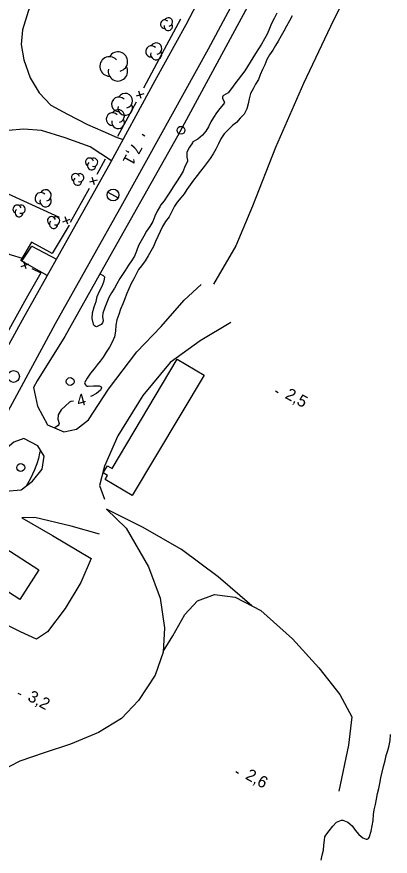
# Model space of a CAD drawing. Extents: x 219136 to 222520, y 5421589 to 5424530.
# Drawn here: x 221431.4 to 221526.7, y 5422722 to 5422936.2 of the extents above; entities that cross this region are included whole.
import ezdxf

# ---------------------------------------------------------------- set-up
doc = ezdxf.new("R2010")
doc.units = 0
for name, color, linetype in [('Level 19', 7, 'Continuous'), ('Level 2', 7, 'Continuous'), ('Level 21', 7, 'Continuous'), ('Level 22', 7, 'Continuous'), ('Level 3', 7, 'Continuous'), ('Level 31', 7, 'Continuous'), ('Level 36', 7, 'Continuous'), ('Level 37', 7, 'Continuous'), ('Level 4', 7, 'Continuous'), ('Level 44', 7, 'Continuous')]:
    doc.layers.add(name, color=color, linetype=linetype)

msp = doc.modelspace()

# ---------------------------------------------------------------- linework, layer by layer
at = {"layer": 'Level 19'}
for points in [[(221444.73, 5422964.58), (221440.63, 5422955.36), (221437.41, 5422946.13), (221434.29, 5422937.53), (221432.86, 5422932.84), (221432.52, 5422929.08), (221433.14, 5422925.22), (221434.77, 5422920.64), (221437.12, 5422916.8), (221440.11, 5422913.61), (221444.29, 5422911.34), (221449.43, 5422908.7), (221453.33, 5422907), (221456.97, 5422905.38), (221458.52, 5422904.9), (221458.52, 5422904.9)], [(221455.56, 5422899.45), (221450.13, 5422902.97), (221443.75, 5422905.28), (221437.65, 5422907.16), (221433.18, 5422907.51), (221429.15, 5422907.19), (221426.47, 5422906.23), (221424.66, 5422905.18), (221423.3, 5422905.9), (221423.99, 5422907.81)], [(221439.15, 5422870.13), (221432.69, 5422873.79), (221435.21, 5422877.69), (221441.53, 5422874.38)], [(221435.61, 5422841.61), (221435.61, 5422841.61), (221436.65, 5422836.82), (221439.23, 5422832.1), (221443.38, 5422830.24), (221446.65, 5422830.99), (221449.7, 5422833.36), (221454.79, 5422841.19), (221462.04, 5422850.67), (221468.26, 5422857.16), (221474.11, 5422863.89), (221478.48, 5422867.89)], [(221486.07, 5422858.15), (221478.17, 5422853.46), (221470.54, 5422848), (221463.6, 5422839.56), (221457.18, 5422829.25), (221453.81, 5422821.54), (221452.51, 5422816.61), (221453.74, 5422813.07)], [(221426.88, 5422822.1), (221426.47, 5422817.72), (221428.51, 5422815.17), (221432.5, 5422815.48), (221435.41, 5422817.66), (221437.85, 5422820.74), (221438.38, 5422824.05), (221436.71, 5422826.7), (221433.19, 5422828.61), (221430.64, 5422827.65), (221428.31, 5422825.67), (221427.3, 5422823.23), (221426.88, 5422822.1)], [(221452.48, 5422804.16), (221445.25, 5422806.19), (221435.99, 5422808.42), (221432.65, 5422808.36), (221440.53, 5422803.81), (221450.33, 5422797.93), (221447.77, 5422791.86), (221443.71, 5422785.23), (221439.24, 5422779.2), (221436.41, 5422777.39), (221432.3, 5422779.27), (221426.3, 5422782.25), (221417.54, 5422786.7), (221413.86, 5422787.79), (221413.2, 5422787.46)]]:
    msp.add_lwpolyline(points, dxfattribs=at)
at = {"layer": 'Level 2'}
for points in [[(221497.8, 5422937.14), (221497.08, 5422935.77), (221496.43, 5422934.5), (221495.87, 5422933.24), (221495.28, 5422931.78), (221494.62, 5422930.53), (221493.89, 5422929.18), (221493.12, 5422928), (221492.37, 5422926.85), (221491.65, 5422925.73), (221490.93, 5422924.63), (221490.29, 5422923.47), (221489.59, 5422922.42), (221488.72, 5422921.27), (221487.92, 5422920.17), (221487.07, 5422919.07), (221486.19, 5422917.9)], [(221501.7, 5422936.4), (221501, 5422935.13), (221500.28, 5422933.79), (221499.59, 5422932.55), (221498.9, 5422931.31), (221498.13, 5422929.94), (221497.45, 5422928.84), (221496.73, 5422927.68), (221495.92, 5422926.47), (221495.21, 5422925.26), (221494.68, 5422923.97), (221494.16, 5422922.77), (221493.56, 5422921.36), (221493.06, 5422920.21), (221492.34, 5422919), (221491.7, 5422917.83)], [(221491.7, 5422917.83), (221491.06, 5422916.59), (221490.72, 5422915.27), (221490.45, 5422913.95), (221490.15, 5422912.69), (221489.41, 5422911.38), (221488.45, 5422910.3), (221487.48, 5422909.19), (221486.5, 5422908.41), (221485.37, 5422907.36), (221484.33, 5422906.32), (221483.51, 5422905.06), (221482.85, 5422903.75), (221482.2, 5422902.41), (221481.48, 5422901.19), (221480.75, 5422900.06), (221480, 5422898.97), (221479.19, 5422897.95), (221478.25, 5422896.76), (221477.4, 5422895.71), (221476.5, 5422894.54), (221475.61, 5422893.29), (221474.81, 5422892.14), (221474.09, 5422891.04), (221473.28, 5422889.95), (221472.35, 5422888.92), (221471.66, 5422887.87), (221470.96, 5422886.53), (221470.29, 5422885.17), (221469.38, 5422883.94), (221468.61, 5422882.68), (221468.03, 5422881.36), (221467.41, 5422880.15), (221466.83, 5422878.83), (221466.25, 5422877.57), (221465.61, 5422876.34), (221464.96, 5422875.21), (221464.12, 5422873.93), (221463.23, 5422872.66), (221462.46, 5422871.67), (221461.87, 5422870.49), (221461.29, 5422869.33), (221460.62, 5422868.15), (221459.97, 5422866.79), (221459.38, 5422865.41), (221458.95, 5422864.23), (221458.43, 5422862.97), (221457.9, 5422861.59), (221457.4, 5422860.22), (221456.93, 5422858.89), (221456.67, 5422857.48), (221456.57, 5422855.96), (221456.3, 5422854.52), (221455.73, 5422853.16), (221455.02, 5422851.85), (221454.21, 5422850.58), (221453.45, 5422849.33), (221452.69, 5422848.31), (221451.88, 5422847.34), (221451.1, 5422846.33), (221450.21, 5422845.24), (221449.32, 5422843.98), (221448.7, 5422842.75), (221448.71, 5422842.49), (221448.88, 5422842.26)], [(221486.19, 5422917.9), (221485.32, 5422916.82), (221484.14, 5422916.14), (221483.95, 5422915.94), (221483.87, 5422915.65), (221483.88, 5422915.4), (221484.01, 5422915.16), (221484.39, 5422914.43), (221484.32, 5422914.16), (221484.19, 5422913.93), (221483.22, 5422912.79), (221482.39, 5422911.7), (221481.63, 5422910.5), (221480.89, 5422909.36), (221480.29, 5422908.15), (221479.68, 5422907), (221478.77, 5422905.94), (221477.61, 5422905), (221476.36, 5422904.28), (221476.24, 5422904.02), (221475.44, 5422902.9), (221474.81, 5422901.67), (221474.78, 5422900.33), (221475.01, 5422899.56), (221474.93, 5422899.28), (221474.28, 5422898.01), (221473.84, 5422896.83), (221473.13, 5422895.56), (221472.13, 5422894.06), (221471.28, 5422892.82), (221470.63, 5422891.7), (221469.8, 5422890.45), (221468.97, 5422889.26), (221468.06, 5422888.14), (221467.96, 5422887.88), (221467.25, 5422886.61), (221466.64, 5422885.3), (221466.1, 5422883.98), (221465.39, 5422882.7), (221464.52, 5422881.48), (221463.82, 5422880.24), (221463.15, 5422879.01), (221462.48, 5422877.81), (221461.94, 5422876.34), (221461.4, 5422875.1), (221460.64, 5422873.94), (221459.89, 5422872.83), (221459.05, 5422871.47), (221458.4, 5422870.39), (221457.67, 5422869.38), (221456.93, 5422868.01), (221456.3, 5422866.93), (221455.59, 5422865.78), (221454.89, 5422864.54), (221454.35, 5422863.25), (221453.86, 5422862.04), (221453.36, 5422860.59), (221453.28, 5422859.69), (221453.42, 5422858.58), (221453.26, 5422858.08), (221452.95, 5422857.63), (221451.74, 5422857.04), (221451.47, 5422857.13), (221451.26, 5422857.3), (221451.06, 5422857.52)], [(221433.08, 5422874.39), (221430.88, 5422875.12), (221429.41, 5422875.52), (221428.17, 5422876.34), (221427.05, 5422877.27), (221425.78, 5422877.81), (221424.5, 5422878.22), (221423.07, 5422878.43), (221421.74, 5422878.54), (221420.36, 5422878.61), (221418.92, 5422878.73), (221417.5, 5422879.14), (221416.17, 5422879.1), (221414.79, 5422878.66), (221413.27, 5422878.51), (221412, 5422878.68)], [(221451.06, 5422857.52), (221450.94, 5422857.76), (221450.6, 5422859.16), (221450.71, 5422860.66), (221451.17, 5422862.14), (221451.63, 5422863.54), (221451.94, 5422864.84), (221452.47, 5422866.14), (221453.18, 5422867.45), (221453.72, 5422868.79), (221453.88, 5422869.72), (221453.71, 5422869.93), (221453.49, 5422870.09), (221452.58, 5422870.56)], [(221448.88, 5422842.26), (221449.09, 5422842.09), (221449.33, 5422841.96), (221449.61, 5422841.9), (221450.99, 5422842), (221452.42, 5422842.02), (221452.94, 5422841.75), (221453, 5422841.48), (221452.93, 5422841.22), (221452.77, 5422840.93), (221451.69, 5422840.04), (221450.46, 5422839.38), (221450.22, 5422839.26)], [(221445.87, 5422838.11), (221445.15, 5422837.99), (221444.86, 5422837.84), (221443.72, 5422836.83), (221442.74, 5422835.85), (221441.9, 5422834.61), (221441.86, 5422833.53), (221442.24, 5422832.44), (221442.1, 5422832.17), (221441.91, 5422831.92), (221441.08, 5422831.27)], [(221437.45, 5422825.53), (221437.2, 5422824.84), (221436.93, 5422823.46), (221436.46, 5422822.07), (221435.89, 5422820.62), (221435.37, 5422819.48), (221434.84, 5422818.34), (221434.13, 5422816.97), (221433.77, 5422816.43)]]:
    msp.add_lwpolyline(points, dxfattribs=at)
at = {"layer": 'Level 21'}
for points in [[(221660.64, 5423258.98), (221639.04, 5423219.11), (221616.62, 5423177.95), (221598.48, 5423145.47), (221572.5, 5423097.61), (221544.2, 5423045.77), (221525.59, 5423011.52), (221501.12, 5422966.85), (221480.22, 5422927.93), (221458.39, 5422888.43), (221441.16, 5422857.84), (221426.14, 5422830.08), (221397.61, 5422779.56)], [(221573.68, 5423090.42), (221550.76, 5423048.84), (221524.85, 5423002.21), (221513.34, 5422981.11), (221496.53, 5422950.29), (221472.38, 5422905.69), (221452.73, 5422870.82), (221443.68, 5422854.61), (221436.62, 5422843.25), (221435.61, 5422841.61)], [(221423.8, 5422850.98), (221425.45, 5422850.43), (221426.75, 5422850.45), (221428.3, 5422851.3), (221429.4, 5422852.61), (221432.84, 5422858.87), (221454.87, 5422898.19), (221466.7, 5422919.93), (221474.59, 5422934.2), (221477.45, 5422939.57), (221478.51, 5422941.89), (221478.75, 5422943.99), (221478.29, 5422946.25), (221477.27, 5422947.93), (221476.62, 5422949.49)]]:
    msp.add_lwpolyline(points, dxfattribs=at)
at = {"layer": 'Level 22'}
for points in [[(221513.34, 5422981.11), (221513.79, 5422980.18), (221515.67, 5422975.98), (221518.52, 5422969.98), (221520.79, 5422963.3), (221521.05, 5422955.96), (221519.28, 5422949.47), (221512.27, 5422935.35), (221504.62, 5422919.16), (221497.4, 5422902.81), (221491.57, 5422887.89), (221487.28, 5422877.77), (221481.59, 5422867.92)], [(221454.3, 5422810.51), (221459.28, 5422805.72), (221464.97, 5422795.86), (221467.99, 5422787.86), (221469.08, 5422780.24), (221468.76, 5422774.06), (221466.75, 5422768.18), (221462.44, 5422761.73), (221458.14, 5422757.08), (221452.23, 5422753.51), (221445.07, 5422750.57), (221438.34, 5422748.37), (221432.15, 5422746.2), (221426.76, 5422743.55), (221422.19, 5422739.04), (221418.14, 5422733.43), (221412.6, 5422722.52), (221397.76, 5422693.4), (221390.31, 5422680.23), (221384.4, 5422671.25), (221379.74, 5422663.83)], [(221491.42, 5422785.85), (221482.77, 5422793.29), (221473.45, 5422800.29), (221463.62, 5422805.85), (221454.3, 5422810.51)], [(221468.77, 5422774.18), (221471.22, 5422778.2), (221474.28, 5422783.63), (221477.55, 5422787.11), (221481.89, 5422788.74), (221487.17, 5422788.05), (221493.7, 5422784.67), (221501.82, 5422777.48), (221508.51, 5422770.03), (221513.87, 5422763.24), (221516.97, 5422757.55), (221516.1, 5422750.35), (221513.59, 5422738.55)]]:
    msp.add_lwpolyline(points, dxfattribs=at)
at = {"layer": 'Level 3'}
for p, q in [((221463.38, 5422906.22), (221464.08, 5422905.84)), ((221497.43, 5422840.72), (221498.14, 5422840.34)), ((221431.68, 5422763.6), (221432.38, 5422763.21)), ((221487.3, 5422743.57), (221488, 5422743.18))]:
    msp.add_line(p, q, dxfattribs=at)
at = {"layer": 'Level 31'}
for points in [[(221479.19, 5422844.74), (221460.88, 5422814.02), (221453.97, 5422818.14), (221454.55, 5422819.12), (221453.43, 5422819.79), (221454.52, 5422821.62), (221455.69, 5422820.92), (221472.33, 5422848.83)], [(221426.78, 5422801.61), (221436.97, 5422795.08), (221432.12, 5422787.51), (221421.93, 5422794.04)]]:
    msp.add_lwpolyline(points, close=True, dxfattribs=at)
at = {"layer": 'Level 36'}
msp.add_line((221454.65, 5422891.46), (221457.25, 5422889.98), dxfattribs=at)
for centre, radius in [((221473.32, 5422907.23), 1), ((221455.96, 5422890.72), 1.5), ((221430.54, 5422844.4), 1.5), ((221445, 5422843.12), 1), ((221432.39, 5422821.16), 1)]:
    msp.add_circle(centre, radius, dxfattribs=at)
at = {"layer": 'Level 37'}
for p, q in [((221463.82, 5422916.55), (221461.9, 5422915.97)), ((221463.15, 5422915.3), (221462.57, 5422917.22)), ((221451.87, 5422894.51), (221449.94, 5422893.97)), ((221451.18, 5422893.28), (221450.63, 5422895.2)), ((221443.11, 5422883.87), (221444.99, 5422884.58)), ((221444.4, 5422883.29), (221443.7, 5422885.16)), ((221432.51, 5422872.5), (221434.41, 5422873.14)), ((221433.77, 5422871.87), (221433.14, 5422873.77))]:
    msp.add_line(p, q, dxfattribs=at)
for points in [[(221468.54, 5422926.83), (221473.27, 5422935.64)], [(221463.8, 5422918.02), (221468.54, 5422926.83)], [(221457.18, 5422905.69), (221461.91, 5422914.5)], [(221451.88, 5422895.99), (221454.07, 5422899.92)], [(221424.03, 5422893.33), (221433.13, 5422889.19)], [(221445.06, 5422883.76), (221449.93, 5422892.49)], [(221433.13, 5422889.19), (221442.23, 5422885.05)], [(221444.76, 5422883.05), (221440.45, 5422875.79), (221439.08, 5422876.53)], [(221439.08, 5422876.53), (221435.16, 5422878.65), (221432.3, 5422873.9)], [(221435.25, 5422871.93), (221437.48, 5422870.81), (221433.8, 5422864.27)], [(221433.8, 5422864.27), (221428.9, 5422855.56)]]:
    msp.add_lwpolyline(points, dxfattribs=at)
at = {"layer": 'Level 4'}
for points in [[(221510.06, 5422726.89), (221510.31, 5422727.36), (221511.16, 5422728.48), (221512.12, 5422729.68), (221512.98, 5422730.65), (221514.31, 5422731.17), (221514.62, 5422731.16), (221515.91, 5422730.71), (221517.01, 5422729.73), (221517.8, 5422728.66), (221518.68, 5422727.52), (221519.74, 5422726.64), (221520.6, 5422726.29), (221520.88, 5422726.35), (221521.15, 5422726.52), (221521.36, 5422726.78), (221521.48, 5422727.01), (221521.89, 5422728.36), (221522.13, 5422729.75), (221522.35, 5422731.13), (221522.46, 5422732.59), (221522.65, 5422733.83), (221522.95, 5422735.16), (221523.2, 5422736.57), (221523.45, 5422737.98), (221523.8, 5422739.25), (221524.08, 5422740.57), (221524.36, 5422741.97), (221524.68, 5422743.39), (221525.05, 5422744.91), (221525.43, 5422746.4), (221525.74, 5422747.66), (221526.09, 5422748.93), (221526.46, 5422750.22), (221526.73, 5422751.5), (221526.82, 5422753)], [(221509.13, 5422720.97), (221509.34, 5422722.21), (221509.67, 5422723.51), (221509.82, 5422724.77), (221509.94, 5422726.09), (221510.06, 5422726.89)]]:
    msp.add_lwpolyline(points, dxfattribs=at)
at = {"layer": 'Level 44'}
for centre, radius, start, end in [((221469.14, 5422934.31), 1.08, 44.1153, 269.8039), ((221470.07, 5422934.85), 1.08, 282.2692, 149.7262), ((221470.07, 5422933.76), 1.08, 166.9368, 29.6212), ((221465.73, 5422927.36), 1.43, 44.1153, 269.8039), ((221466.96, 5422928.08), 1.43, 282.2692, 149.7262), ((221457.21, 5422924.76), 2.48, 282.2692, 149.7262), ((221466.96, 5422926.64), 1.43, 166.9368, 29.6212), ((221455.07, 5422923.52), 2.48, 44.1153, 269.8039), ((221457.21, 5422922.28), 2.48, 166.9368, 29.6212), ((221457.45, 5422913.84), 1.87, 44.1153, 269.8039), ((221459.07, 5422914.78), 1.87, 282.2692, 149.7262), ((221459.07, 5422912.9), 1.87, 166.9368, 29.6212), ((221455.85, 5422910.06), 1.62, 44.1153, 269.8039), ((221457.24, 5422910.87), 1.62, 282.2692, 149.7262), ((221457.24, 5422909.25), 1.62, 166.9368, 29.6212), ((221449.95, 5422899.09), 1.05, 15.9068, 238.5912), ((221450.46, 5422898.18), 1.05, 131.2391, 358.6962), ((221451, 5422899.07), 1.05, 253.0853, 118.7739), ((221446.39, 5422895.14), 1.05, 15.9068, 238.5912), ((221446.9, 5422894.23), 1.05, 131.2391, 358.6962), ((221447.44, 5422895.12), 1.05, 253.0853, 118.7739), ((221437.48, 5422889.88), 1.45, 44.1153, 269.8039), ((221438.73, 5422890.61), 1.45, 282.2692, 149.7262), ((221431.45, 5422887.11), 1.05, 15.9068, 238.5912), ((221432.5, 5422887.09), 1.05, 253.0853, 118.7739), ((221438.73, 5422889.16), 1.45, 166.9368, 29.6212), ((221431.96, 5422886.2), 1.05, 131.2391, 358.6962), ((221440.25, 5422884.14), 1.05, 15.9068, 238.5912), ((221440.76, 5422883.23), 1.05, 131.2391, 358.6962), ((221441.3, 5422884.12), 1.05, 253.0853, 118.7739)]:
    msp.add_arc(centre, radius, start, end, dxfattribs=at)

# ---------------------------------------------------------------- texts
at = {"layer": 'Level 2'}
msp.add_text('4', height=3, rotation=15.4798, dxfattribs=at).set_placement((221447.13, 5422836.67))
at = {"layer": 'Level 3'}
for s, rotation, p in [('7,1', 241.0864, (221460.99, 5422904.27)), ('2,5', 331.383, (221499.68, 5422838.99)), ('3,2', 331.383, (221433.92, 5422761.86)), ('2,6', 331.383, (221489.54, 5422741.83))]:
    msp.add_text(s, height=3, rotation=rotation, dxfattribs=at).set_placement(p)

doc.saveas('drawing.dxf')
